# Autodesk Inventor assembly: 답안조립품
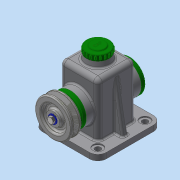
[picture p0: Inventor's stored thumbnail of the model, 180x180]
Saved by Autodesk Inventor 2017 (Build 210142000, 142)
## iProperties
Part Number: 답안조립품
Material: 일반
Document SubType Name: Assembly
Designer: MRC
Author: MRC
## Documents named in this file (14)
- C:\Users\MRC\Desktop\700907V1004\답안조립품.iam
- C:\Users\MRC\Desktop\700907V1004\Ű 5 x 5 x 14.ipt
- C:\Users\MRC\Desktop\700907V1004\V-벨트풀리.ipt
- C:\Users\MRC\Desktop\700907V1004\뒤커버.ipt
- C:\Users\MRC\Desktop\700907V1004\멈춤링 15 x 1.ipt
- C:\Users\MRC\Desktop\700907V1004\베어링 15 x 35 x 11.ipt
- C:\Users\MRC\Desktop\700907V1004\본체.ipt
- C:\Users\MRC\Desktop\700907V1004\볼트 M4 x 10.ipt
- C:\Users\MRC\Desktop\700907V1004\볼트 M6 x 12.ipt
- C:\Users\MRC\Desktop\700907V1004\상부캡.ipt
- C:\Users\MRC\Desktop\700907V1004\앞커버.ipt
- C:\Users\MRC\Desktop\700907V1004\오일실 15 25 7.ipt
- C:\Users\MRC\Desktop\700907V1004\와셔.ipt
- C:\Users\MRC\Desktop\700907V1004\축.ipt
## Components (2 placed, 2 different names)
1. Ű 5 x 5 x 14:1
2. V-벨트풀리:1
